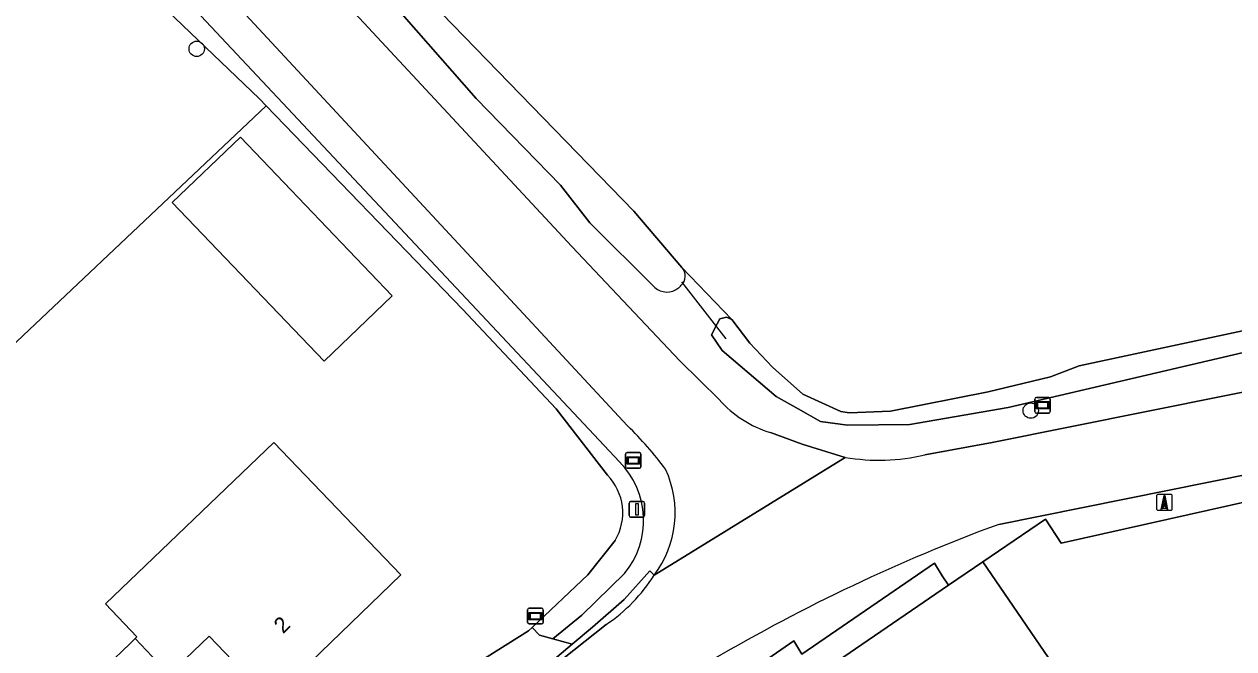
# Model space of a CAD drawing. Extents: x 164494 to 166241, y 382475 to 384495.
# Drawn here: x 165354.5 to 165431.6, y 384074.7 to 384114.4 of the extents above; entities that cross this region are included whole.
import ezdxf

# ---------------------------------------------------------------- set-up
doc = ezdxf.new("R2010")
doc.units = 0
for name, color, linetype in [('IMGEO_Berm_halfverhard', 7, 'Continuous'), ('IMGEO_Boom', 7, 'Continuous'), ('IMGEO_Duiker', 7, 'Continuous'), ('IMGEO_Erf', 7, 'Continuous'), ('IMGEO_Groenvoorziening', 7, 'Continuous'), ('IMGEO_Laagspanningsmast', 7, 'Continuous'), ('IMGEO_Lichtmast', 7, 'Continuous'), ('IMGEO_Loofbos', 7, 'Continuous'), ('IMGEO_Pand', 7, 'Continuous'), ('IMGEO_Pand_nummerreeks', 7, 'Continuous'), ('IMGEO_Rijbaan_lokaal_gesloten', 7, 'Continuous'), ('IMGEO_Straatnaambord', 7, 'Continuous'), ('IMGEO_Voetpad_open', 7, 'Continuous'), ('IMGEO_Waterloop', 7, 'Continuous'), ('IMGEO_Wegwijzer', 7, 'Continuous')]:
    doc.layers.add(name, color=color, linetype=linetype)

msp = doc.modelspace()

# ---------------------------------------------------------------- linework, layer by layer
at = {"layer": 'IMGEO_Berm_halfverhard'}
msp.add_lwpolyline([(165394.648, 384079.364), (165394.369, 384079.637), (165392.734, 384077.813), (165390.73, 384076.059), (165389.436, 384074.97), (165388.458, 384074.147), (165383.832, 384070.529), (165380.649, 384068.04), (165380.854, 384067.745), (165387.482, 384072.953), (165391.605, 384076.232)], dxfattribs=at)
msp.add_arc((165385.679, 384085.034), 10.611, 303.95118, 327.70031, dxfattribs=at)
at = {"layer": 'IMGEO_Boom'}
for centre in [(165365.505, 384112.881), (165418.65, 384089.844)]:
    msp.add_circle(centre, 0.489, dxfattribs=at)
at = {"layer": 'IMGEO_Duiker'}
msp.add_lwpolyline([(165399.238, 384094.405), (165396.409, 384098.046)], dxfattribs=at)
at = {"layer": 'IMGEO_Erf'}
for points in [[(165391.678, 384085.733), (165388.411, 384089.95), (165382.449, 384096.307), (165369.932, 384109.251), (165348.615, 384089.13), (165324.577, 384114.294), (165317.6, 384108.966), (165252.153, 384058.979), (165253.127, 384057.056), (165268.295, 384067.905), (165290.735, 384085.47), (165292.37, 384086.749), (165313.785, 384064.085), (165326.891, 384050.086), (165329.75, 384047.033), (165339.009, 384037.144), (165341.59, 384039.543), (165343.541, 384040.983), (165347.115, 384043.622), (165350.846, 384047.468), (165352.53, 384048.91)], [(165452.198, 384086.5), (165450.367, 384088.075), (165420.581, 384081.409), (165419.584, 384082.942), (165415.596, 384080.216), (165421.157, 384072.086), (165417.913, 384069.799), (165420.915, 384066.582), (165414.624, 384060.384), (165410.357, 384064.715), (165408.991, 384063.791), (165403.577, 384071.996), (165413.421, 384078.728), (165412.998, 384079.325), (165412.511, 384080.132), (165404.074, 384074.333), (165403.548, 384075.178), (165393.462, 384068.193), (165394.614, 384066.341)], [(165379.994, 384071.652), (165383.268, 384073.701), (165386.651, 384075.818), (165386.877, 384076.031), (165390.423, 384079.385), (165392.167, 384081.577)]]:
    msp.add_lwpolyline(points, dxfattribs=at)
for points in [[(165363.946, 384103.101), (165368.288, 384107.259), (165377.967, 384097.162), (165373.627, 384093.002)], [(165370.222, 384071.391), (165367.373, 384068.646), (165362.702, 384064.146), (165361.201, 384062.699), (165356.175, 384057.856), (165352.706, 384061.457), (165347.988, 384066.354), (165354.518, 384072.645), (165354.686, 384072.807), (165356.732, 384070.685), (165361.259, 384075.024), (165361.593, 384075.344), (165361.693, 384075.439), (165359.686, 384077.533), (165370.419, 384087.822), (165372.426, 384085.728), (165378.512, 384079.379)]]:
    msp.add_lwpolyline(points, close=True, dxfattribs=at)
msp.add_arc((165389.234, 384083.339), 3.421, 329.01008, 44.41119, dxfattribs=at)
at = {"layer": 'IMGEO_Groenvoorziening'}
for points in [[(165392.958, 384088.876), (165346.214, 384139.179), (165268.809, 384221.915), (165262.693, 384228.453)], [(165349.898, 384142.75), (165389.399, 384100.284), (165396.286, 384093.011), (165398.793, 384090.547)], [(165358.298, 384122.953), (165392.452, 384086.579)], [(165394.693, 384097.693), (165390.566, 384101.804), (165388.691, 384104.19), (165383.315, 384109.711), (165374.128, 384120.184)], [(165497.556, 384095.525), (165506.541, 384097.437), (165516.619, 384099.573), (165520.078, 384100.258), (165522.619, 384102.163), (165522.854, 384102.571), (165522.974, 384102.779), (165522.403, 384102.657), (165519.48, 384102.032), (165519.212, 384101.976), (165519.156, 384102.326), (165523.094, 384103.146), (165523.158, 384103.389), (165523.28, 384103.856), (165516.675, 384102.818), (165474.797, 384094.323), (165456.979, 384090.714), (165416.608, 384082.604)], [(165437.748, 384094.84), (165417.214, 384090.034), (165410.945, 384088.97), (165406.968, 384088.922), (165405.247, 384089.149), (165403.826, 384089.958), (165402.437, 384090.749), (165398.999, 384093.665), (165398.311, 384094.68), (165398.676, 384095.366), (165398.845, 384095.684), (165399.263, 384095.787), (165399.604, 384095.649), (165396.427, 384098.959)], [(165411.913, 384087.024), (165416.203, 384087.817), (165455.965, 384095.8)], [(165402.065, 384088.445), (165404.092, 384087.709), (165406.821, 384086.869)], [(165394.614, 384066.341), (165393.462, 384068.193), (165403.548, 384075.178), (165404.074, 384074.333), (165412.511, 384080.132), (165412.998, 384079.325), (165413.421, 384078.728), (165415.596, 384080.216), (165419.584, 384082.942), (165420.581, 384081.409), (165450.367, 384088.075), (165452.198, 384086.5)], [(165392.761, 384079.482), (165390.041, 384076.822), (165388.208, 384075.306), (165389.436, 384074.97), (165390.73, 384076.059), (165392.734, 384077.813), (165394.369, 384079.637), (165394.648, 384079.364)]]:
    msp.add_lwpolyline(points, dxfattribs=at)
msp.add_lwpolyline([(165356.604, 384122.555), (165348.288, 384131.158), (165347.388, 384132.202), (165325.92, 384115.348), (165324.577, 384114.294), (165348.615, 384089.13), (165369.932, 384109.251), (165369.504, 384109.693), (165363.145, 384115.787)], close=True, dxfattribs=at)
for centre, radius, start, end in [((165395.84, 384098.42), 0.797, 311.76739, 42.57338), ((165395.469, 384098.56), 1.164, 228.18853, 308.92258), ((165395.476, 384098.55), 1.152, 308.97442, 321.02558), ((165404.215, 384095.389), 7.269, 221.76652, 252.79843), ((165378.228, 384073.548), 21.259, 36.21195, 46.13939), ((165408.98, 384099.656), 12.968, 260.41552, 283.07156), ((165388.729, 384082.862), 5.261, 320.03276, 44.95335), ((165389.472, 384083.337), 6.525, 322.48932, 25.11949), ((165456.825, 383973.925), 115.881, 110.3071, 120.27508)]:
    msp.add_arc(centre, radius, start, end, dxfattribs=at)
at = {"layer": 'IMGEO_Laagspanningsmast'}
for p, q in [((165426.671, 384084.414), (165426.671, 384083.573)), ((165426.671, 384084.414), (165426.671, 384083.573)), ((165427.587, 384084.498), (165426.746, 384084.498)), ((165427.587, 384084.498), (165426.746, 384084.498)), ((165427.671, 384083.582), (165427.671, 384084.423)), ((165427.671, 384083.582), (165427.671, 384084.423)), ((165427.33, 384083.608), (165427.005, 384083.608)), ((165427.062, 384083.901), (165427.011, 384083.639)), ((165427.011, 384083.639), (165427.157, 384083.799)), ((165427.167, 384083.788), (165427.019, 384083.629)), ((165427.019, 384083.629), (165427.316, 384083.629)), ((165427.157, 384083.799), (165427.062, 384083.901)), ((165427.116, 384084.178), (165427.068, 384083.929)), ((165427.068, 384083.929), (165427.162, 384084.097)), ((165427.074, 384083.911), (165427.167, 384083.809)), ((165427.26, 384083.911), (165427.074, 384083.911)), ((165427.167, 384084.088), (165427.078, 384083.929)), ((165427.078, 384083.929), (165427.256, 384083.929)), ((165427.162, 384084.097), (165427.116, 384084.178)), ((165427.119, 384084.19), (165427.214, 384084.19)), ((165427.126, 384084.178), (165427.167, 384084.106)), ((165427.207, 384084.178), (165427.126, 384084.178)), ((165427.167, 384084.106), (165427.207, 384084.178)), ((165427.256, 384083.929), (165427.167, 384084.088)), ((165427.167, 384083.809), (165427.26, 384083.911)), ((165427.316, 384083.629), (165427.167, 384083.788)), ((165427.217, 384084.178), (165427.172, 384084.097)), ((165427.172, 384084.097), (165427.266, 384083.929)), ((165427.272, 384083.901), (165427.177, 384083.799)), ((165427.177, 384083.799), (165427.324, 384083.639)), ((165427.266, 384083.929), (165427.217, 384084.178)), ((165427.324, 384083.639), (165427.272, 384083.901)), ((165426.755, 384083.498), (165427.596, 384083.498)), ((165426.755, 384083.498), (165427.596, 384083.498))]:
    msp.add_line(p, q, dxfattribs=at)
for points in [[(165427.005, 384083.608), (165426.994, 384083.55), (165426.969, 384083.55), (165427.145, 384084.438), (165427.166, 384084.446), (165427.19, 384084.439), (165427.367, 384083.55), (165427.341, 384083.55), (165427.33, 384083.608)], [(165427.214, 384084.19), (165427.166, 384084.432), (165427.119, 384084.19)]]:
    msp.add_lwpolyline(points, dxfattribs=at)
for centre, start, end in [((165426.749, 384084.42), 92.4484, 184.28452), ((165426.749, 384084.42), 92.4484, 184.28452), ((165427.593, 384084.42), 2.4484, 94.28452), ((165427.593, 384084.42), 2.4484, 94.28452), ((165426.749, 384083.576), 182.4484, 274.28452), ((165426.749, 384083.576), 182.4484, 274.28452), ((165427.593, 384083.576), 272.4484, 4.28452), ((165427.593, 384083.576), 272.4484, 4.28452)]:
    msp.add_arc(centre, 0.0779, start, end, dxfattribs=at)
at = {"layer": 'IMGEO_Lichtmast'}
for p, q in [((165393.057, 384083.156), (165393.057, 384083.956)), ((165393.057, 384083.956), (165393.057, 384083.156)), ((165393.157, 384084.056), (165393.947, 384084.056)), ((165393.947, 384084.056), (165393.157, 384084.056)), ((165394.047, 384083.956), (165394.047, 384083.156)), ((165394.047, 384083.156), (165394.047, 384083.956)), ((165393.947, 384083.056), (165393.157, 384083.056)), ((165393.157, 384083.056), (165393.947, 384083.056))]:
    msp.add_line(p, q, dxfattribs=at)
msp.add_lwpolyline([(165393.477, 384083.931), (165393.627, 384083.931), (165393.627, 384083.181), (165393.477, 384083.181), (165393.477, 384083.931)], dxfattribs=at)
for centre, start, end in [((165393.157, 384083.956), 90, 180), ((165393.157, 384083.956), 90, 180), ((165393.947, 384083.956), 0, 90), ((165393.947, 384083.956), 360, 90), ((165393.157, 384083.156), 180, 270), ((165393.157, 384083.156), 180, 270), ((165393.947, 384083.156), 270, 0), ((165393.947, 384083.156), 270, 0)]:
    msp.add_arc(centre, 0.1, start, end, dxfattribs=at)
at = {"layer": 'IMGEO_Loofbos'}
msp.add_lwpolyline([(165376.045, 384120.378), (165393.36, 384102.543), (165396.427, 384098.959), (165399.604, 384095.649), (165400.755, 384094.137), (165402.204, 384092.608), (165404.135, 384090.901), (165406.542, 384089.799), (165407.082, 384089.702), (165409.719, 384089.801), (165415.947, 384091.045), (165419.918, 384091.993), (165421.732, 384092.686), (165437.2, 384096.016), (165444.307, 384097.307), (165449.115, 384098.581), (165451.793, 384098.76), (165453.309, 384099.19), (165465.666, 384101.993)], dxfattribs=at)
at = {"layer": 'IMGEO_Pand'}
for points in [[(165373.627, 384093.002), (165377.967, 384097.162), (165368.288, 384107.259), (165363.946, 384103.101)], [(165378.512, 384079.379), (165372.426, 384085.728), (165370.419, 384087.822), (165359.686, 384077.533), (165361.693, 384075.439), (165361.593, 384075.344), (165363.752, 384073.045), (165366.29, 384075.484), (165370.222, 384071.391)], [(165413.421, 384078.728), (165403.577, 384071.996), (165408.991, 384063.791), (165410.357, 384064.715), (165414.624, 384060.384), (165420.915, 384066.582), (165417.913, 384069.799), (165421.157, 384072.086), (165415.596, 384080.216)], [(165362.702, 384064.146), (165367.373, 384068.646), (165370.222, 384071.391), (165366.29, 384075.484), (165363.752, 384073.045), (165361.593, 384075.344), (165361.259, 384075.024), (165356.732, 384070.685), (165354.686, 384072.807), (165354.518, 384072.645)]]:
    msp.add_lwpolyline(points, close=True, dxfattribs=at)
at = {"layer": 'IMGEO_Rijbaan_lokaal_gesloten'}
for points in [[(165272.492, 384225.434), (165266.437, 384231.901), (165262.693, 384228.453), (165268.809, 384221.915), (165346.214, 384139.179), (165392.958, 384088.876)], [(165398.793, 384090.547), (165396.286, 384093.011), (165389.399, 384100.284), (165349.898, 384142.75), (165272.492, 384225.434)], [(165456.979, 384090.714), (165455.965, 384095.8), (165416.203, 384087.817), (165411.913, 384087.024)], [(165416.608, 384082.604), (165456.979, 384090.714)], [(165394.648, 384079.364), (165406.821, 384086.869), (165404.092, 384087.709), (165402.065, 384088.445)], [(165406.821, 384086.869), (165394.648, 384079.364)], [(165391.605, 384076.232), (165387.482, 384072.953), (165380.854, 384067.745), (165380.141, 384067.277), (165361.803, 384052.529), (165353.778, 384045.772), (165339.3, 384032.977), (165339.311, 384032.965), (165342.18, 384029.647), (165342.192, 384029.633), (165342.196, 384029.629), (165342.774, 384030.162), (165349.337, 384036.022), (165357.153, 384042.664), (165368.742, 384052.317), (165379.087, 384060.555), (165384.606, 384064.9), (165389.473, 384068.311), (165394.851, 384071.884), (165398.403, 384074.002)]]:
    msp.add_lwpolyline(points, dxfattribs=at)
for centre, radius, start, end in [((165404.215, 384095.389), 7.269, 221.76652, 252.79843), ((165378.228, 384073.548), 21.259, 36.21195, 46.13939), ((165408.98, 384099.656), 12.968, 260.41552, 283.07156), ((165389.472, 384083.337), 6.525, 322.48932, 25.11949), ((165456.825, 383973.925), 115.881, 110.3071, 120.27508), ((165385.679, 384085.034), 10.611, 303.95118, 327.70031)]:
    msp.add_arc(centre, radius, start, end, dxfattribs=at)
at = {"layer": 'IMGEO_Straatnaambord'}
for p, q in [((165392.825, 384086.272), (165392.825, 384087.072)), ((165392.825, 384087.072), (165392.825, 384086.272)), ((165392.925, 384087.172), (165393.715, 384087.172)), ((165393.715, 384087.172), (165392.925, 384087.172)), ((165393.815, 384087.072), (165393.815, 384086.272)), ((165393.815, 384086.272), (165393.815, 384087.072)), ((165393.715, 384086.172), (165392.925, 384086.172)), ((165392.925, 384086.172), (165393.715, 384086.172))]:
    msp.add_line(p, q, dxfattribs=at)
for points in [[(165392.926, 384086.904), (165393.714, 384086.904), (165393.714, 384086.44), (165392.926, 384086.44), (165392.926, 384086.904)], [(165392.991, 384086.839), (165392.991, 384086.505), (165393.649, 384086.505), (165393.649, 384086.839), (165392.991, 384086.839)]]:
    msp.add_lwpolyline(points, dxfattribs=at)
for centre, start, end in [((165392.925, 384087.072), 90, 180), ((165392.925, 384087.072), 90, 180), ((165393.715, 384087.072), 0, 90), ((165393.715, 384087.072), 360, 90), ((165392.925, 384086.272), 180, 270), ((165392.925, 384086.272), 180, 270), ((165393.715, 384086.272), 270, 0), ((165393.715, 384086.272), 270, 0)]:
    msp.add_arc(centre, 0.1, start, end, dxfattribs=at)
at = {"layer": 'IMGEO_Voetpad_open'}
msp.add_lwpolyline([(165388.458, 384074.147), (165389.436, 384074.97), (165388.208, 384075.306), (165387.345, 384075.542), (165386.877, 384076.031), (165386.651, 384075.818), (165383.268, 384073.701), (165383.832, 384070.529)], close=True, dxfattribs=at)
at = {"layer": 'IMGEO_Waterloop'}
for points in [[(165318.076, 384165.691), (165310.986, 384172.785), (165310.432, 384172.859), (165310.026, 384172.859), (165309.556, 384172.648), (165309.264, 384172.258), (165309.118, 384171.918), (165309.079, 384171.594), (165315.877, 384164.356), (165320.438, 384159.316), (165335.97, 384142.707), (165347.388, 384132.202), (165348.288, 384131.158), (165356.604, 384122.555), (165363.145, 384115.787), (165369.504, 384109.693), (165369.932, 384109.251), (165382.449, 384096.307), (165388.411, 384089.95), (165391.678, 384085.733)], [(165439.583, 384138.151), (165437.401, 384141.531), (165433.763, 384147.168), (165424.622, 384163.247), (165422.162, 384166.203), (165420.973, 384167.631), (165409.791, 384160.684), (165396.676, 384151.593), (165378.91, 384138.554), (165369.913, 384131.533), (165367.854, 384130.316), (165367.242, 384129.763), (165366.631, 384129.21), (165366.614, 384128.67), (165366.938, 384128.092), (165367.722, 384127.477), (165369.29, 384125.534), (165370.242, 384124.355), (165374.128, 384120.184), (165383.315, 384109.711), (165388.691, 384104.19), (165390.566, 384101.804), (165394.693, 384097.693)], [(165392.452, 384086.579), (165358.298, 384122.953), (165356.547, 384124.817), (165354.29, 384127.521), (165351.373, 384130.199), (165341.909, 384140.37), (165338.933, 384143.148), (165335.465, 384147.522), (165318.076, 384165.691)], [(165396.427, 384098.959), (165393.36, 384102.543), (165376.045, 384120.378), (165371.059, 384125.95), (165369.983, 384127.153), (165369.194, 384128.508), (165368.786, 384129.525), (165371.845, 384132.306), (165379.838, 384138.363), (165397.437, 384150.983), (165410.628, 384160.2), (165419.903, 384165.794), (165426.11, 384155.983), (165431.819, 384145.094), (165434.692, 384140.895), (165436.544, 384138.189), (165443.618, 384129.92), (165449.748, 384122.324), (165456.299, 384114.591), (165462.24, 384108.193)], [(165437.2, 384096.016), (165421.732, 384092.686), (165419.918, 384091.993), (165415.947, 384091.045), (165409.719, 384089.801), (165407.082, 384089.702), (165406.542, 384089.799), (165404.135, 384090.901), (165402.204, 384092.608), (165400.755, 384094.137), (165399.604, 384095.649), (165399.263, 384095.787), (165398.845, 384095.684), (165398.676, 384095.366), (165398.311, 384094.68), (165398.999, 384093.665), (165402.437, 384090.749), (165403.826, 384089.958), (165405.247, 384089.149), (165406.968, 384088.922), (165410.945, 384088.97), (165417.214, 384090.034), (165437.748, 384094.84)], [(165392.167, 384081.577), (165390.423, 384079.385), (165386.877, 384076.031), (165387.345, 384075.542), (165388.208, 384075.306), (165390.041, 384076.822), (165392.761, 384079.482)]]:
    msp.add_lwpolyline(points, dxfattribs=at)
for centre, radius, start, end in [((165395.84, 384098.42), 0.797, 311.76739, 42.57338), ((165395.469, 384098.56), 1.164, 228.18853, 308.92258), ((165395.476, 384098.55), 1.152, 308.97442, 321.02558), ((165388.729, 384082.862), 5.261, 320.03276, 44.95335), ((165389.234, 384083.339), 3.421, 329.01008, 44.41119)]:
    msp.add_arc(centre, radius, start, end, dxfattribs=at)
at = {"layer": 'IMGEO_Wegwijzer'}
for p, q in [((165418.908, 384089.784), (165418.908, 384090.584)), ((165418.908, 384090.584), (165418.908, 384089.784)), ((165419.008, 384090.684), (165419.798, 384090.684)), ((165419.798, 384090.684), (165419.008, 384090.684)), ((165419.898, 384090.584), (165419.898, 384089.784)), ((165419.898, 384089.784), (165419.898, 384090.584)), ((165419.798, 384089.684), (165419.008, 384089.684)), ((165419.008, 384089.684), (165419.798, 384089.684)), ((165386.592, 384076.364), (165386.592, 384077.164)), ((165386.592, 384077.164), (165386.592, 384076.364)), ((165386.692, 384077.264), (165387.482, 384077.264)), ((165387.482, 384077.264), (165386.692, 384077.264)), ((165387.582, 384077.164), (165387.582, 384076.364)), ((165387.582, 384076.364), (165387.582, 384077.164)), ((165387.482, 384076.264), (165386.692, 384076.264)), ((165386.692, 384076.264), (165387.482, 384076.264))]:
    msp.add_line(p, q, dxfattribs=at)
for points in [[(165419.009, 384090.416), (165419.797, 384090.416), (165419.797, 384089.952), (165419.009, 384089.952), (165419.009, 384090.416)], [(165419.074, 384090.351), (165419.074, 384090.017), (165419.732, 384090.017), (165419.732, 384090.351), (165419.074, 384090.351)], [(165386.693, 384076.996), (165387.481, 384076.996), (165387.481, 384076.532), (165386.693, 384076.532), (165386.693, 384076.996)], [(165386.758, 384076.931), (165386.758, 384076.597), (165387.416, 384076.597), (165387.416, 384076.931), (165386.758, 384076.931)]]:
    msp.add_lwpolyline(points, dxfattribs=at)
for centre, start, end in [((165419.008, 384090.584), 90, 180), ((165419.008, 384090.584), 90, 180), ((165419.798, 384090.584), 0, 90), ((165419.798, 384090.584), 360, 90), ((165419.008, 384089.784), 180, 270), ((165419.008, 384089.784), 180, 270), ((165419.798, 384089.784), 270, 0), ((165419.798, 384089.784), 270, 0), ((165386.692, 384077.164), 90, 180), ((165386.692, 384077.164), 90, 180), ((165387.482, 384077.164), 0, 90), ((165387.482, 384077.164), 360, 90), ((165386.692, 384076.364), 180, 270), ((165386.692, 384076.364), 180, 270), ((165387.482, 384076.364), 270, 0), ((165387.482, 384076.364), 270, 0)]:
    msp.add_arc(centre, 0.1, start, end, dxfattribs=at)

# ---------------------------------------------------------------- texts
at = {"layer": 'IMGEO_Pand_nummerreeks'}
msp.add_text('2', height=1, rotation=44.19796, dxfattribs=at).set_placement((165371.012, 384075.6))

doc.saveas('drawing.dxf')
